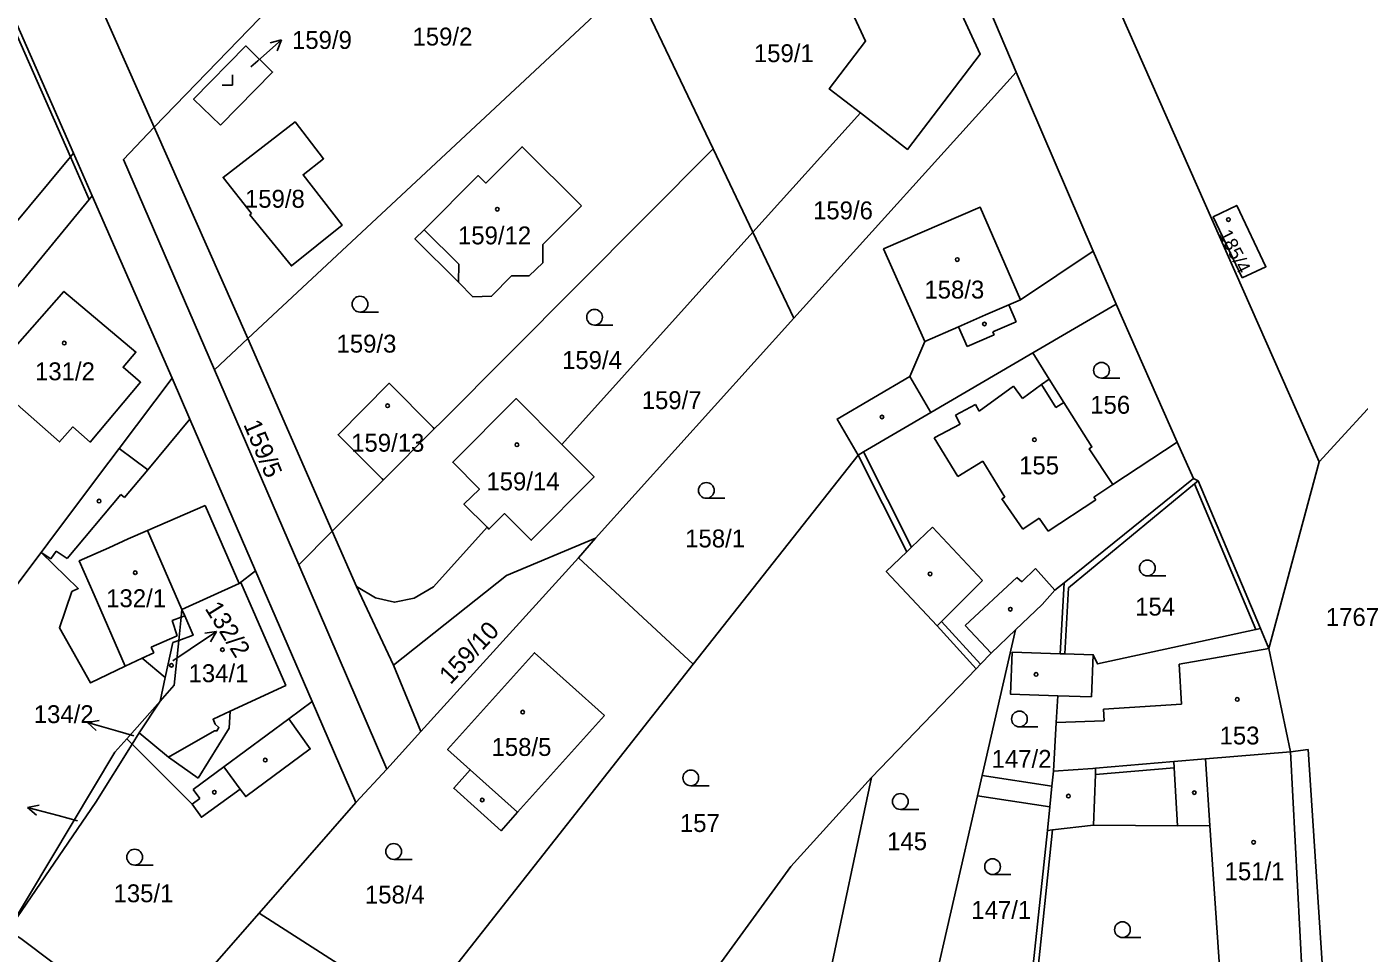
# Model space of a CAD drawing. Extents: x -724107 to -720612, y -1045267 to -1038441.
# Drawn here: x -722946.8 to -722820.2, y -1042451.2 to -1042363.1 of the extents above; entities that cross this region are included whole.
import ezdxf

# ---------------------------------------------------------------- set-up
doc = ezdxf.new("R2010")
doc.units = 0
for name, color, linetype in [('Hranice parcel', 7, 'Continuous'), ('Parcelní čísla', 7, 'Continuous'), ('Pop  PČ popisy', 7, 'Continuous'), ('Vnitřní kresba', 7, 'Continuous'), ('Značky budov', 7, 'Continuous'), ('Značky kultur', 7, 'Continuous')]:
    doc.layers.add(name, color=color, linetype=linetype)

msp = doc.modelspace()

# ---------------------------------------------------------------- linework, layer by layer
at = {"layer": 'Hranice parcel'}
for p, q in [((-722875.11, -1042288.78), (-722824.01, -1042404.46)), ((-722824.01, -1042404.46), (-722733.27, -1042305.52)), ((-722942.37, -1042375.13), (-722952.19, -1042352.7)), ((-722915.19, -1042352.47), (-722934.71, -1042372.64)), ((-722925.82, -1042392.75), (-722889.27, -1042358.62)), ((-722889.27, -1042358.62), (-722881.59, -1042374.72)), ((-722852.81, -1042367.41), (-722856.42, -1042358.89)), ((-722852.81, -1042367.41), (-722873.92, -1042390.81)), ((-722845.47, -1042384.43), (-722852.81, -1042367.41)), ((-722877.81, -1042382.64), (-722867.6, -1042371.3)), ((-722934.71, -1042372.64), (-722925.82, -1042392.75)), ((-722881.59, -1042374.72), (-722877.81, -1042382.64)), ((-722940.6, -1042379.18), (-722942.37, -1042375.13)), ((-722940.6, -1042379.18), (-722933.01, -1042396.52)), ((-722895.97, -1042402.81), (-722877.81, -1042382.64)), ((-722877.81, -1042382.64), (-722873.92, -1042390.81)), ((-722843.31, -1042389.48), (-722845.47, -1042384.43)), ((-722843.31, -1042389.48), (-722851.22, -1042394.11)), ((-722837.49, -1042402.58), (-722843.31, -1042389.48)), ((-722873.92, -1042390.81), (-722892.78, -1042411.71)), ((-722925.82, -1042392.75), (-722917.78, -1042411.06)), ((-722908.09, -1042401.33), (-722912.93, -1042406.19)), ((-722835.95, -1042406.04), (-722837.49, -1042402.58)), ((-722867.82, -1042403.82), (-722883.48, -1042423.7)), ((-722824.01, -1042404.46), (-722828.78, -1042422.22)), ((-722917.78, -1042411.06), (-722912.93, -1042406.19)), ((-722835.95, -1042406.04), (-722848.24, -1042415.96)), ((-722917.78, -1042411.06), (-722915.47, -1042416.3)), ((-722892.78, -1042411.71), (-722894.39, -1042413.6)), ((-722959.73, -1042432.07), (-722945.45, -1042413.08)), ((-722894.39, -1042413.6), (-722909.38, -1042430.11)), ((-722894.39, -1042413.6), (-722883.48, -1042423.7)), ((-722925.07, -1042414.81), (-722919.69, -1042427.24)), ((-722911.96, -1042423.78), (-722915.47, -1042416.3)), ((-722848.62, -1042422.7), (-722848.24, -1042415.96)), ((-722828.78, -1042422.22), (-722829.57, -1042420.31)), ((-722856.04, -1042434.28), (-722852.87, -1042420.44)), ((-722826.74, -1042432.03), (-722828.78, -1042422.22)), ((-722909.38, -1042430.11), (-722911.96, -1042423.78)), ((-722883.48, -1042423.7), (-722909.7, -1042456.98)), ((-722856.61, -1042424.15), (-722866.54, -1042434.46)), ((-722933.66, -1042424.98), (-722934.15, -1042427.22)), ((-722937.32, -1042430.78), (-722934.15, -1042427.22)), ((-722919.69, -1042427.24), (-722915.53, -1042436.86)), ((-722909.38, -1042430.11), (-722912.59, -1042433.67)), ((-722937.32, -1042430.78), (-722936.79, -1042431.31)), ((-722912.59, -1042433.67), (-722915.53, -1042436.86)), ((-722849.41, -1042435.3), (-722856.04, -1042434.28)), ((-722849.41, -1042435.3), (-722849.26, -1042433.88)), ((-722870.73, -1042454.14), (-722866.54, -1042434.46)), ((-722915.53, -1042436.86), (-722924.73, -1042447.38)), ((-722851.81, -1042458.31), (-722849.83, -1042439.52)), ((-722913.77, -1042454.38), (-722924.73, -1042447.38))]:
    msp.add_line(p, q, dxfattribs=at)
for points in [[(-722959.26, -1042316.99), (-722948.46, -1042341.61), (-722934.71, -1042372.64)], [(-722867.6, -1042371.3), (-722870.56, -1042369.01), (-722867.11, -1042364.49), (-722872, -1042353.96), (-722870.86, -1042353.43), (-722874.03, -1042346.62), (-722867.76, -1042343.73), (-722864.6, -1042350.51), (-722863.49, -1042349.99), (-722858.37, -1042361.05)], [(-722858.37, -1042361.05), (-722856.21, -1042365.7), (-722863.13, -1042374.77), (-722867.6, -1042371.3)], [(-722928.41, -1042372.45), (-722930.96, -1042369.98), (-722926.01, -1042364.93), (-722923.46, -1042367.41), (-722928.41, -1042372.45)], [(-722925.45, -1042380.85), (-722928.16, -1042377.43), (-722921.32, -1042372.15), (-722918.61, -1042375.66), (-722920.56, -1042377.17), (-722916.86, -1042381.97), (-722921.67, -1042385.84), (-722925.61, -1042380.97), (-722925.45, -1042380.85)], [(-722934.71, -1042372.64), (-722937.63, -1042375.73), (-722928.99, -1042395.71), (-722920.97, -1042414.27), (-722912.59, -1042433.67)], [(-722894.11, -1042380.12), (-722897.79, -1042383.82), (-722897.79, -1042385.54), (-722899.08, -1042386.78), (-722900.75, -1042386.77), (-722902.65, -1042388.72), (-722904.42, -1042388.77), (-722905.78, -1042387.38), (-722909.93, -1042383.28), (-722909.06, -1042382.4), (-722903.93, -1042377.25), (-722903.2, -1042377.97), (-722899.75, -1042374.51), (-722894.11, -1042380.12)], [(-722908.09, -1042401.33), (-722907.41, -1042400.65), (-722881.59, -1042374.72)], [(-722974.34, -1042413.56), (-722942.67, -1042375.48), (-722942.37, -1042375.13)], [(-722950.37, -1042391.04), (-722940.89, -1042379.53), (-722940.6, -1042379.18)], [(-722867.82, -1042403.82), (-722869.82, -1042400.4), (-722862.9, -1042396.36), (-722861.48, -1042393.01), (-722865.39, -1042384.23), (-722856.22, -1042380.24), (-722852.38, -1042389.05), (-722845.47, -1042384.43)], [(-722831.31, -1042386.98), (-722834.07, -1042381.17), (-722831.83, -1042380.09), (-722829.06, -1042385.92), (-722831.31, -1042386.98)], [(-722947.7, -1042393.27), (-722943.29, -1042388.26), (-722936.45, -1042394.03), (-722937.67, -1042395.48), (-722936, -1042396.9), (-722940.79, -1042402.59), (-722942.44, -1042401.14), (-722943.69, -1042402.57), (-722950.46, -1042396.64)], [(-722851.22, -1042394.11), (-722860.9, -1042399.78), (-722867.3, -1042403.52), (-722867.82, -1042403.82)], [(-722837.49, -1042402.58), (-722843.6, -1042406.63), (-722845.86, -1042403.22), (-722845.6, -1042403.05), (-722848.26, -1042398.82), (-722849.66, -1042396.59), (-722851.22, -1042394.11)], [(-722945.45, -1042413.08), (-722944.81, -1042412.22), (-722940, -1042405.81), (-722938.02, -1042403.19), (-722933.01, -1042396.52)], [(-722933.01, -1042396.52), (-722931.32, -1042400.41), (-722925.07, -1042414.81)], [(-722912.93, -1042406.19), (-722913.04, -1042406.08), (-722917.24, -1042401.89), (-722912.38, -1042396.99), (-722908.21, -1042401.21), (-722908.09, -1042401.33)], [(-722903.08, -1042410.69), (-722905.27, -1042408.48), (-722903.8, -1042407.05), (-722906.34, -1042404.5), (-722900.32, -1042398.45), (-722895.97, -1042402.81)], [(-722895.97, -1042402.81), (-722892.9, -1042405.89), (-722898.88, -1042411.92), (-722901.43, -1042409.38), (-722902.9, -1042410.87), (-722903.08, -1042410.69)], [(-722867.82, -1042403.82), (-722863.2, -1042413.03), (-722865.14, -1042414.89), (-722860.32, -1042420.05), (-722856.61, -1042424.15)], [(-722829.57, -1042420.31), (-722835.51, -1042406.26), (-722835.95, -1042406.04)], [(-722915.47, -1042416.3), (-722913.69, -1042417.4), (-722911.86, -1042417.81), (-722910.01, -1042417.43), (-722908.17, -1042416.35), (-722903.08, -1042410.69)], [(-722911.96, -1042423.78), (-722901.24, -1042415.28), (-722892.78, -1042411.71)], [(-722945.45, -1042413.08), (-722941.93, -1042416.52), (-722942.52, -1042416.79), (-722943.71, -1042420.24), (-722940.77, -1042425.48), (-722937.47, -1042423.88), (-722935.86, -1042423.13), (-722933.66, -1042424.98)], [(-722932.37, -1042421.44), (-722932.14, -1042419.23), (-722932.07, -1042418.51), (-722926.63, -1042416.02), (-722925.07, -1042414.81)], [(-722848.24, -1042415.96), (-722849.13, -1042416.67), (-722850.32, -1042418.03), (-722852.87, -1042420.44)], [(-722829.57, -1042420.31), (-722830.01, -1042420.41), (-722845.06, -1042423.67), (-722845.47, -1042422.8), (-722848.17, -1042422.71), (-722848.62, -1042422.7)], [(-722934.15, -1042427.22), (-722932.8, -1042425.7), (-722932.37, -1042421.44)], [(-722933.66, -1042424.98), (-722932.92, -1042421.64), (-722932.37, -1042421.44)], [(-722852.87, -1042420.44), (-722855.18, -1042422.66), (-722856.19, -1042423.71), (-722856.61, -1042424.15)], [(-722891.92, -1042428.59), (-722900.17, -1042437.78), (-722901.74, -1042439.53), (-722906.24, -1042435.49), (-722904.67, -1042433.74), (-722906.83, -1042431.8), (-722898.58, -1042422.61), (-722891.92, -1042428.59)], [(-722849.26, -1042433.88), (-722849, -1042429.25), (-722848.85, -1042426.7), (-722853.33, -1042426.56), (-722853.17, -1042422.57), (-722848.62, -1042422.7)], [(-722934.15, -1042427.22), (-722936.12, -1042430.24), (-722936.79, -1042431.31)], [(-722936.79, -1042431.31), (-722931.11, -1042437.02), (-722930.22, -1042438.25), (-722926.53, -1042435.57), (-722926, -1042436.28), (-722919.87, -1042431.76), (-722921.9, -1042428.88), (-722919.69, -1042427.24)], [(-722948.59, -1042449), (-722938.46, -1042432.07), (-722937.32, -1042430.78)], [(-722936.79, -1042431.31), (-722940.24, -1042436.82), (-722948.59, -1042449)], [(-722849.26, -1042433.88), (-722845.52, -1042433.61), (-722845.25, -1042433.59), (-722837.83, -1042432.96), (-722834.82, -1042432.71), (-722826.74, -1042432.03)], [(-722825.61, -1042453.34), (-722825.62, -1042453.26), (-722826.74, -1042432.03)], [(-722860.98, -1042455.87), (-722856.48, -1042436.21), (-722856.04, -1042434.28)], [(-722866.54, -1042434.46), (-722874.22, -1042442.93), (-722890.07, -1042464.77)], [(-722849.83, -1042439.52), (-722849.61, -1042437.27), (-722849.41, -1042435.3)], [(-722833.38, -1042453.83), (-722834.39, -1042439.02), (-722837.47, -1042439.07), (-722845.44, -1042438.99), (-722849.33, -1042439.46), (-722849.83, -1042439.52)], [(-722924.73, -1042447.38), (-722932.73, -1042456.52), (-722933.62, -1042457.53)], [(-722940.77, -1042453.62), (-722944.3, -1042452.1), (-722947.37, -1042449.77), (-722948.59, -1042449)]]:
    msp.add_lwpolyline(points, dxfattribs=at)
at = {"layer": 'Pop  PČ popisy'}
for p, q in [((-722924.87, -1042366.33), (-722922.6, -1042364.36)), ((-722922.6, -1042364.36), (-722923.69, -1042364.64)), ((-722922.6, -1042364.36), (-722923.03, -1042365.4)), ((-722925.52, -1042366.9), (-722924.87, -1042366.33)), ((-722931.28, -1042422.28), (-722928.79, -1042420.6)), ((-722928.79, -1042420.6), (-722929.9, -1042420.75)), ((-722928.79, -1042420.6), (-722929.34, -1042421.58)), ((-722932.93, -1042423.39), (-722931.28, -1042422.28)), ((-722941.05, -1042429.25), (-722939.94, -1042429.05)), ((-722938.16, -1042430.08), (-722941.05, -1042429.25)), ((-722941.05, -1042429.25), (-722940.22, -1042430.01)), ((-722936.65, -1042430.52), (-722938.16, -1042430.08)), ((-722946.74, -1042437.31), (-722945.64, -1042437.09)), ((-722943.84, -1042438.09), (-722946.74, -1042437.31)), ((-722946.74, -1042437.31), (-722945.9, -1042438.06)), ((-722941.98, -1042438.6), (-722943.84, -1042438.09))]:
    msp.add_line(p, q, dxfattribs=at)
at = {"layer": 'Vnitřní kresba'}
for p, q in [((-722942.67, -1042375.48), (-722952.59, -1042352.87)), ((-722940.89, -1042379.53), (-722942.67, -1042375.48)), ((-722909.06, -1042382.4), (-722905.76, -1042385.66)), ((-722905.76, -1042385.66), (-722905.78, -1042387.38)), ((-722855.7, -1042390.49), (-722853.5, -1042389.54)), ((-722853.5, -1042389.54), (-722852.38, -1042389.05)), ((-722853.5, -1042389.54), (-722852.8, -1042391.16)), ((-722858.29, -1042391.62), (-722855.7, -1042390.49)), ((-722852.8, -1042391.16), (-722855, -1042392.11)), ((-722861.48, -1042393.01), (-722858.29, -1042391.62)), ((-722857.47, -1042393.51), (-722858.29, -1042391.62)), ((-722854.88, -1042392.38), (-722857.47, -1042393.51)), ((-722855, -1042392.11), (-722854.88, -1042392.38)), ((-722925.82, -1042392.75), (-722928.99, -1042395.71)), ((-722862.9, -1042396.36), (-722860.9, -1042399.78)), ((-722856.32, -1042399.64), (-722853.06, -1042397.27)), ((-722853.06, -1042397.27), (-722852.21, -1042398.44)), ((-722852.21, -1042398.44), (-722850.39, -1042397.12)), ((-722850.39, -1042397.12), (-722849.66, -1042396.59)), ((-722850.39, -1042397.12), (-722849.03, -1042399.3)), ((-722848.26, -1042398.82), (-722849.03, -1042399.3)), ((-722858.55, -1042400.03), (-722856.65, -1042399.02)), ((-722858.11, -1042400.87), (-722858.55, -1042400.03)), ((-722856.65, -1042399.02), (-722856.32, -1042399.64)), ((-722931.32, -1042400.41), (-722935.32, -1042405.22)), ((-722860.59, -1042402.18), (-722858.11, -1042400.87)), ((-722858.34, -1042405.87), (-722860.59, -1042402.18)), ((-722938.02, -1042403.19), (-722935.32, -1042405.22)), ((-722867.3, -1042403.52), (-722862.75, -1042412.59)), ((-722935.32, -1042405.22), (-722937.52, -1042407.86)), ((-722855.95, -1042404.41), (-722858.34, -1042405.87)), ((-722853.87, -1042407.81), (-722855.95, -1042404.41)), ((-722835.51, -1042406.26), (-722835.86, -1042406.55)), ((-722937.87, -1042407.57), (-722942.98, -1042413.64)), ((-722937.52, -1042407.86), (-722937.87, -1042407.57)), ((-722847.82, -1042416.43), (-722835.86, -1042406.55)), ((-722843.6, -1042406.63), (-722845.41, -1042407.83)), ((-722835.86, -1042406.55), (-722830.01, -1042420.41)), ((-722929.86, -1042408.61), (-722935.33, -1042410.99)), ((-722926.63, -1042416.02), (-722929.86, -1042408.61)), ((-722854.17, -1042407.99), (-722853.87, -1042407.81)), ((-722852.17, -1042410.85), (-722854.17, -1042407.99)), ((-722845.24, -1042408.08), (-722849.76, -1042411.07)), ((-722845.41, -1042407.83), (-722845.24, -1042408.08)), ((-722850.6, -1042409.81), (-722852.17, -1042410.85)), ((-722849.76, -1042411.07), (-722850.6, -1042409.81)), ((-722935.33, -1042410.99), (-722937.18, -1042411.79)), ((-722935.33, -1042410.99), (-722932.07, -1042418.51)), ((-722917.78, -1042411.06), (-722920.97, -1042414.27)), ((-722860.75, -1042410.67), (-722862.75, -1042412.59)), ((-722860.75, -1042410.67), (-722855.99, -1042415.73)), ((-722939.03, -1042412.63), (-722937.18, -1042411.79)), ((-722863.2, -1042413.03), (-722862.75, -1042412.59)), ((-722945.45, -1042413.08), (-722944.52, -1042413.69)), ((-722944.52, -1042413.69), (-722944.03, -1042412.95)), ((-722944.03, -1042412.95), (-722942.98, -1042413.64)), ((-722850.97, -1042414.6), (-722852.27, -1042415.88)), ((-722849.13, -1042416.67), (-722850.97, -1042414.6)), ((-722855.99, -1042415.73), (-722859.9, -1042419.63)), ((-722852.74, -1042415.45), (-722857.64, -1042420.03)), ((-722852.27, -1042415.88), (-722852.74, -1042415.45)), ((-722847.82, -1042416.43), (-722848.17, -1042422.71)), ((-722940.42, -1042417.1), (-722937.47, -1042423.88)), ((-722932.14, -1042419.23), (-722931.81, -1042419.11)), ((-722931.81, -1042419.11), (-722932.07, -1042418.51)), ((-722860.32, -1042420.05), (-722859.9, -1042419.63)), ((-722856.19, -1042423.71), (-722859.9, -1042419.63)), ((-722857.64, -1042420.03), (-722855.18, -1042422.66)), ((-722932.52, -1042420.99), (-722934.99, -1042422.07)), ((-722934.74, -1042422.61), (-722935.86, -1042423.13)), ((-722934.99, -1042422.07), (-722934.74, -1042422.61)), ((-722845.47, -1042422.8), (-722845.65, -1042426.8)), ((-722828.78, -1042422.22), (-722837.3, -1042423.71)), ((-722837.3, -1042423.71), (-722837.09, -1042427.51)), ((-722845.65, -1042426.8), (-722848.85, -1042426.7)), ((-722837.09, -1042427.51), (-722844.51, -1042427.98)), ((-722844.51, -1042427.98), (-722844.44, -1042429.07)), ((-722921.9, -1042428.88), (-722928.09, -1042433.46)), ((-722844.44, -1042429.07), (-722849, -1042429.25)), ((-722936.12, -1042430.24), (-722933.36, -1042432.54)), ((-722825.06, -1042431.81), (-722826.74, -1042432.03)), ((-722822.89, -1042465.05), (-722825.06, -1042431.81)), ((-722930.52, -1042434.54), (-722933.36, -1042432.54)), ((-722837.83, -1042432.96), (-722837.79, -1042433.56)), ((-722834.82, -1042432.71), (-722834.39, -1042439.02)), ((-722928.09, -1042433.46), (-722931.01, -1042435.62)), ((-722926.53, -1042435.57), (-722928.09, -1042433.46)), ((-722904.67, -1042433.74), (-722900.17, -1042437.78)), ((-722845.44, -1042438.99), (-722845.27, -1042434.19)), ((-722845.27, -1042434.19), (-722837.79, -1042433.56)), ((-722845.25, -1042433.59), (-722845.27, -1042434.19)), ((-722837.47, -1042439.07), (-722837.79, -1042433.56)), ((-722931.01, -1042435.62), (-722930.37, -1042436.48)), ((-722930.37, -1042436.48), (-722931.11, -1042437.02)), ((-722856.48, -1042436.21), (-722849.61, -1042437.27)), ((-722849.33, -1042439.46), (-722851.26, -1042457.87))]:
    msp.add_line(p, q, dxfattribs=at)
for points in [[(-722940.42, -1042417.1), (-722941.83, -1042413.89), (-722939.03, -1042412.63)], [(-722927.48, -1042428.17), (-722922.21, -1042425.72), (-722926.46, -1042415.94), (-722926.63, -1042416.02)], [(-722932.37, -1042421.44), (-722931.01, -1042420.95), (-722931.81, -1042419.11)], [(-722932.14, -1042419.23), (-722932.99, -1042419.56), (-722932.52, -1042420.99)], [(-722933.36, -1042432.54), (-722928.97, -1042430.05), (-722928.75, -1042430.05), (-722928.56, -1042429.73), (-722928.9, -1042429.4), (-722929.11, -1042428.93), (-722927.48, -1042428.17)], [(-722927.48, -1042428.17), (-722927.58, -1042429.78), (-722930.52, -1042434.54)]]:
    msp.add_lwpolyline(points, dxfattribs=at)
at = {"layer": 'Značky budov'}
for centre in [(-722902.1, -1042380.45), (-722832.63, -1042381.43), (-722858.4, -1042385.24), (-722855.82, -1042391.36), (-722943.25, -1042393.18), (-722912.53, -1042399.13), (-722865.55, -1042400.2), (-722900.24, -1042402.84), (-722851.06, -1042402.36), (-722939.94, -1042408.2), (-722936.51, -1042415), (-722860.98, -1042415.12), (-722853.35, -1042418.47), (-722928.22, -1042422.32), (-722933.07, -1042423.81), (-722850.9, -1042424.67), (-722831.79, -1042427.05), (-722899.69, -1042428.25), (-722924.15, -1042432.82), (-722928.99, -1042435.87), (-722903.54, -1042436.61), (-722847.83, -1042436.24), (-722835.87, -1042435.91), (-722830.24, -1042440.62)]:
    msp.add_circle(centre, 0.175, dxfattribs=at)
at = {"layer": 'Značky kultur'}
for p, q in [((-722927.25, -1042368.67), (-722927.25, -1042367.67)), ((-722928.25, -1042368.67), (-722927.25, -1042368.67)), ((-722915.15, -1042390.23), (-722913.4, -1042390.23)), ((-722892.86, -1042391.47), (-722891.11, -1042391.47)), ((-722844.69, -1042396.51), (-722842.94, -1042396.51)), ((-722882.24, -1042407.93), (-722880.49, -1042407.93)), ((-722840.34, -1042415.3), (-722838.59, -1042415.3)), ((-722852.49, -1042429.66), (-722850.74, -1042429.66)), ((-722883.72, -1042435.26), (-722881.97, -1042435.26)), ((-722863.8, -1042437.5), (-722862.05, -1042437.5)), ((-722936.56, -1042442.79), (-722934.81, -1042442.79)), ((-722911.95, -1042442.25), (-722910.2, -1042442.25)), ((-722855.04, -1042443.7), (-722853.29, -1042443.7)), ((-722842.7, -1042449.69), (-722840.95, -1042449.69))]:
    msp.add_line(p, q, dxfattribs=at)
for centre in [(-722915.15, -1042389.48), (-722892.86, -1042390.72), (-722844.69, -1042395.76), (-722882.24, -1042407.18), (-722840.34, -1042414.55), (-722852.49, -1042428.91), (-722883.72, -1042434.51), (-722863.8, -1042436.75), (-722936.56, -1042442.04), (-722911.95, -1042441.5), (-722855.04, -1042442.95), (-722842.7, -1042448.94)]:
    msp.add_circle(centre, 0.75, dxfattribs=at)

# ---------------------------------------------------------------- texts
at = {"layer": 'Parcelní čísla'}
for s, p in [('159/9', (-722921.61, -1042365.21)), ('159/2', (-722910.16, -1042364.89)), ('159/1', (-722877.72, -1042366.47)), ('159/8', (-722926.08, -1042380.31)), ('159/6', (-722872.1, -1042381.41)), ('159/12', (-722905.84, -1042383.79)), ('158/3', (-722861.52, -1042388.94)), ('159/3', (-722917.38, -1042394.08)), ('131/2', (-722946.03, -1042396.71)), ('159/4', (-722895.95, -1042395.64)), ('159/7', (-722888.38, -1042399.45)), ('156', (-722845.76, -1042399.89)), ('159/13', (-722915.99, -1042403.5)), ('155', (-722852.52, -1042405.65)), ('159/14', (-722903.14, -1042407.17)), ('158/1', (-722884.25, -1042412.6)), ('132/1', (-722939.27, -1042418.28)), ('154', (-722841.49, -1042419.08)), ('1767', (-722823.37, -1042420.06)), ('134/1', (-722931.44, -1042425.41)), ('134/2', (-722946.15, -1042429.3)), ('153', (-722833.47, -1042431.33)), ('158/5', (-722902.65, -1042432.42)), ('147/2', (-722855.13, -1042433.55)), ('157', (-722884.75, -1042439.65)), ('145', (-722865.06, -1042441.38)), ('151/1', (-722832.99, -1042444.24)), ('135/1', (-722938.57, -1042446.33)), ('158/4', (-722914.68, -1042446.45)), ('147/1', (-722857.06, -1042447.91))]:
    msp.add_text(s, height=1.7, dxfattribs=at).set_placement(p)
for s, height, rotation, p in [('185/4', 1.3, 297, (-722833.59, -1042382.79)), ('159/5', 1.7, 293, (-722926.26, -1042400.9)), ('132/2', 1.7, 302, (-722929.94, -1042418.4)), ('159/10', 1.7, 47, (-722906.55, -1042425.71))]:
    msp.add_text(s, height=height, rotation=rotation, dxfattribs=at).set_placement(p)

doc.saveas('drawing.dxf')
